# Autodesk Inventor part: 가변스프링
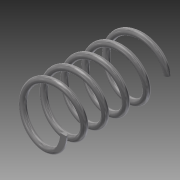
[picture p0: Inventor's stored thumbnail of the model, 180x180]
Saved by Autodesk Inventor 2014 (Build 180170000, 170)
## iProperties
Created: 2017-02
Part Number: 가변스프링
Material: 강철, 탄소
Document SubType Name: Modeling
Designer: owner
Density: 7.87 g/cm^3
Appearance: 반연마
Mass: 6.52146 g
Surface Area: 16.8149 cm^2
Volume: 0.828648 cm^3
Author: owner
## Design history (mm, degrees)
sketch "스케치1"
  geometry: L1 (0, 0)-(8.5, 0); L2 (8.5, 0)-(8.5, 35); L3 (8.5, 35)-(0, 35); L4 (0, 35)-(0, 0); C1 r 1 at (8.5, 0)
  constraints: 8 end point, 2 parallel, 1 centre point, 1 coincident, 1 horizontal, 1 perpendicular
  dimensions: "d0" = 17 diameter of L2.end L4; "d1" = 35 distance of L1.end L2.end (derived); "d2" = 2 diameter of C1
feature "코일1" sketch "스케치1" pitch "d3" = 10; turns "d5" = 5; dims "d4" = 35 (= d1), "d6" = 0, angle "d7" = 90 deg, angle "d8" = 90 deg, "d9" = 0, "d10" = 0
sketch "스케치2"
  geometry: L1 (-9.5, 0)-(-7.5, 0) reference; L2 (-9.5, 0)-(-7.5, 0) reference; 1 further point
  constraints: 2 horizontal alignment
extrude "돌출1" cut sketch "스케치2" stored distance "d11" = 10; taper "d12" = 0 deg
node "작업 평면1"
sketch "스케치3"
  geometry: L1 (1, 0)-(-1, 0) reference; 1 further point
  constraints: 1 horizontal alignment
extrude "돌출2" cut sketch "스케치3" stored distance "d13" = 10; taper "d14" = 0 deg
node "솔리드1"
node "절단 모서리 투영1"
node "절단 모서리 투영2"
node "절단 모서리 투영3"
